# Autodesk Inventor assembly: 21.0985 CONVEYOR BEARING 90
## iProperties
Created: 2007-07
Part Number: 21.0985 CONVEYOR BEARING 90
Document SubType Name: Assembly
Designer: Andy Moles
Author: Andy Moles
